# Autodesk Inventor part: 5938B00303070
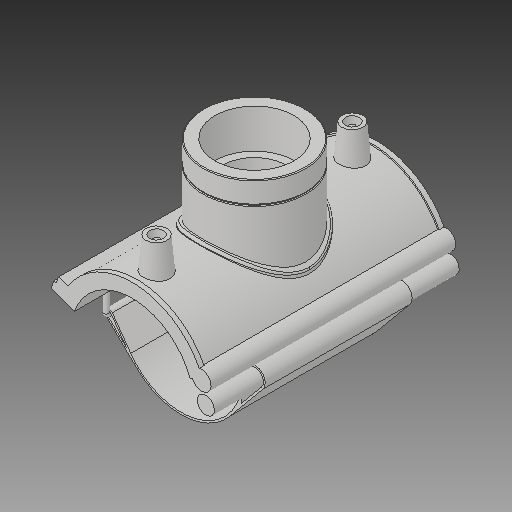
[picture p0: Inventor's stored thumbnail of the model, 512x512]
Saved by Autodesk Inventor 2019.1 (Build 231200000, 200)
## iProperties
Created: 2017-07
Part Number: 5938B00303070
Material: Generic
Description: PLASSON TRANSITION SADDLE 3''IPS x 2"NPT
Document SubType Name: Modeling
Designer: KIM
Density: 1 g/cm^3
Appearance: Default
Author: KIM
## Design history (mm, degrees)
derived "5938B.ipt"
feature "Solid1::5938B.ipt"
tag "TaggingFeature1"
body "Solid1"
other parameters: "d0" = 88.7, "d1" = 106.44, "d2" = 341.63, "d3" = 22.175, "d4" = 176.022, "d5" = 0, "d40" = 55.3488, "d41" = 79.3184, "d43" = 0, "d45" = 0, "d47" = 99.956, "d48" = 73.6528, "d50" = 0, "d78" = 75.22, "d79" = 15, "d80" = 70.4088, "d82" = 5 deg, "d84" = 4, "d85" = 14, "d86" = 0, "d87" = 3, "d88" = 0, "d96" = 108.5688, "d97" = 3.52044, "d98" = 0, "d102" = 1.69968, "d103" = 56.656, "d104" = 28.0416, "d105" = 0, "d106" = 45.3248, "d108" = 0, "d109" = -15.57867, "d111" = 0.5, "d112" = 0.5, "d113" = 0, "d114" = 0.5, "d117" = 0.56656, "d120" = 140 deg, "d121" = 24.228, "d122" = 20 deg, "d123" = 425.76, "d124" = 63.864, "d126" = 0, "d143" = 91.361, "d145" = 13.64615, "d149" = 1.3305, "d150" = 15.01077, "d153" = 176.022, "d154" = 0, "d156" = 53.22, "d157" = 160 deg, "d159" = 3.548, "d161" = 1.3305, "d162" = 105.6132, "d163" = 0, "d164" = 44.35, "d167" = 8.87, "d168" = 51.92195, "d170" = 1.3305, "d172" = 0, "d173" = 1, "d175" = 44.35, "d176" = 20 deg, "d177" = 6.209, "d178" = 17.74, "d180" = 0, "d183" = 7.096, "d184" = 4.9672, "d185" = 57.20715, "d186" = 57.20715, "d187" = 53.22, "d188" = 5.322, "d189" = 6.209, "d190" = 0, "d191" = 63.864, "d193" = 3.548, "d194" = 1.81835, "d195" = 90 deg, "d197" = 0, "d199" = 0, "d_" = 88.7, "B_" = 136.652, "H_" = 46.736, "L_" = 176.022, "d_t" = 6, "G_" = 56.656, "d148" = 1.3305, "d160" = 1.3305, "d169" = 1.3305, "d192" = 3.548
